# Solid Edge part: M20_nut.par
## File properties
Title: Ecrou hexagonal NF EN 1661 - M20 - 8
Author: TraceParts S.A.
Template: Iso Metric Part.par
Last saved by: Nimesh.N
Revision: 4
Application: TraceParts
Company: TraceParts S.A.
Density: 7833.000 kg/m^3
Accuracy: 0.990
REFERENCE: NF EN 1661 - d M20 - 8
STANDARD: NF EN 1661
NOTE: Classe: 8
DESIGN: Ecrou hexagonal NF EN 1661 - M20 - 8
MATERIAL: Acier
TraceParts.PartNumber: 10-13082008-066825
TraceParts.PartLanguage: fr
TraceParts.InstanceId: 10-13082008-0668255NKFB0O5CP5B1M9CKK2QV8UDW
TraceParts.PartStandardAcronym: NF
TraceParts.PartTitle: Ecrous hexagonaux à embase cylindro-tronconique
TRACEPARTS: TRACEPARTS
TraceParts.PartVersion: 1.2.4
Username: Nimesh.N
Material: Steel
Face Style: Steel
Fill Style: ANSI32(Steel)
Virtual Style: Machined steel
Grouping: Metals\Steel
LibraryName: Materials
Coef. of Thermal Exp: 1.3e-05
Thermal Conductivity: 32.0
Specific Heat: 481.0
Modulus of Elasticity: 199947953000.0
Poisson's Ratio: 0.29
Yield Stress: 262000766.0
Ultimate Stress: 358527364.0
Elongation: 0.0
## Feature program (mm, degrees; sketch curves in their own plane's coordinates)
body "unnamed Body 1"
sketch for "unnamed Cutout 1" plane through (0, 0, 0) normal (0, 0, -1) x-axis (1, 0, 0)
  circle centre (0, 0) radius 10
extrude "unnamed Cutout 1" cut through along -normal
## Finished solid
Body 1: solid body, 17 faces, 34 edges, 20 vertices.
  Faces by surface: plane 8, cone 7, cylinder 1, torus 1
  Edges by curve: spline 18, circle 10, line 6
Bounding box of the edges (mm; curved faces can reach further): 41.350 x 41.350 x 20.000, from (-20.675, -20.675, 0) to (20.675, 20.675, 20).
Cylindrical faces by radius (mm): R10 x1
Conical faces (half-angle, radius in mm at the cone's reference point): 60 deg R10.3375 x1, 60 deg R16.1625 x6
Toroidal faces (ring radius, tube radius in mm): R19.95 r1.45 x1
Planar faces by outward normal: +x 1, +z 1, -x 1, -z 1, oblique 4
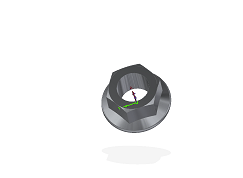
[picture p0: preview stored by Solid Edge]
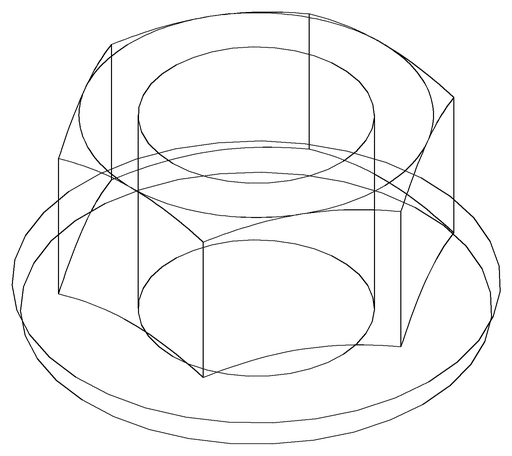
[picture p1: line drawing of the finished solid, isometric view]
